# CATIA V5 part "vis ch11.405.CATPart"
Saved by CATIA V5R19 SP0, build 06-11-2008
Part number: vis ch11.406
Bounding box of the stored display mesh (mm): x 0 to 7.4, y -1.3 to 1.3, z -1.3 to 1.3
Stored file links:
  G:\project guitar elect\vis ch11.405.CATPart
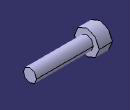
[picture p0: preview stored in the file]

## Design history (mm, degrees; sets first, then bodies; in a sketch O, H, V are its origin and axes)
Body1 (main body)
  Sketch1 on yz-plane, origin (0, 0, 0), H (0, 1, 0), V (0, 0, 1)
    circle A1 centre (0, 0) radius 1.3
    radius A1 = 1.3
  Pad1: profile Sketch1, direction (1, 0, 0), length 1.4
  Sketch2 on end face of Pad1, origin (1.4, 0, 0), H (0, 1, 0), V (0, 0, 1)
    circle A1 centre (0, 0) radius 0.7
    radius A1 = 0.7
  Pad2: profile Sketch2, direction (1, 0, 0), length 6
  Sketch3 on start face of Pad1, origin (0, 0, 0), H (0, -1, 0), V (0, 0, 1)
    point P1 (0.5914, -0.2697)
    line L1 (0.5914, -0.2697) -> (0.5914, 0.2697)
    point P2 (0.5914, 0.2697)
    line L2 (0.5914, 0.2697) -> (0, 0.65)
    point P3 (0, 0.65)
    line L3 (0.5914, -0.2697) -> (0, -0.65)
    point P4 (0, -0.65)
    axis line L4 (0, 0.8043) -> (0, -0.9585)
    point P5 (0, 0.8043)
    point P7 (0, -0.65)
    point P8 (-0.5914, -0.2697)
    line L5 (-0.5914, -0.2697) -> (0, -0.65)
    point P9 (-0.5914, 0.2697)
    line L6 (-0.5914, -0.2697) -> (-0.5914, 0.2697)
    point P10 (0, 0.65)
    line L7 (-0.5914, 0.2697) -> (0, 0.65)
    vertical: L1 V, L4 V
    coincidence: P3 V, P4 V, P5 V, P3 P10, P4 P7
    symmetry: P4 P7 L4, P1 P8 L4, L3 L5 L4, P2 P9 L4, L1 L6 L4, P3 P10 L4, L2 L7 L4
  Pocket1: profile Sketch3, direction (1, 0, 0), length 1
